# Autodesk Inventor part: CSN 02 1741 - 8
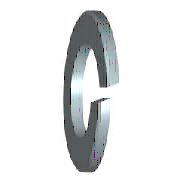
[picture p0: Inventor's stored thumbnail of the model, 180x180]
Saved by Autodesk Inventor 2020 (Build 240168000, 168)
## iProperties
Created: 2019-01
Part Number: CSN 02 1741 - 8
Material: Ocel, měkká
Description: Pružné podložky obdélníkového průřezu
Document SubType Name: Modeling
Standard: CSN 02 1741
Designer: doma
Standards Organization: CSN
Language: cs-CZ
Size Designation: 8
Categories: <MemberInstance><Categories><Category DisplayName="Spojovací materiál" InternalName="e4da775c-781d-43d5-af7c-5136215cf5a6" Mnemonic="FSTN"><Category DisplayName
Density: 7.85 g/cm^3
Appearance: Pololeštěná
IsCustomPart: 0
Author: doma
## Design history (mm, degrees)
sketch "Náčrt1"
  geometry: C1 r 7.1 at (0, 0); C2 r 4.1 at (0, 0); 1 further point
  constraints: 2 centre point, 2 coincident
  dimensions: "d0" = 8.2 diameter of C2 (= SD1); "d1" = 14.2 diameter of C1 (= SD2)
extrude "Těleso" new body sketch "Náčrt1" distance "d2" = 2 (= SD); taper "d3" = 0 deg
sketch "Náčrt2"
  geometry: L1 (0, -4.1)-(0, 4.1) reference; L2 (2, 7.1)-(2, -7.1) reference; L3 (-1.2, 0)-(7.2, 0) reference; L4 (0, -0.4)-(2, -0.047); L5 (0, 0.4)-(2, 0.753)
  constraints: 4 end point, 4 point on line, 1 parallel
  dimensions: "d4" = 0.4 distance from line of L3 L4.start (= 0.2 x SD); "d5" = 0.4 distance from line of L3 L5.start (= 0.2 x SD); "d6" = 80 deg angle of L2 L4 (= FAWI)
extrude "Výřez" cut sketch "Náčrt2" stored distance "d7" = 2 (= SD); taper "d8" = 0 deg
workaxis "Work Axis1"
workplane "Work Plane1"
body "Solid1"
other parameters: "SD1" = 8.2 [user parameter; used in 1 equation term], "SD2" = 14.2 [user parameter; used in 1 equation term], "SD" = 2 [user parameter; used in 4 equation terms], "FAWI" = 80 deg [user parameter; used in 1 equation term], "d9" = 0, "d10" = 0, "d11" = 0, "d12" = 0, "NND" = 8 [user parameter]
